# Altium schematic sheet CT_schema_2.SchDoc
size 308 x 312 mm
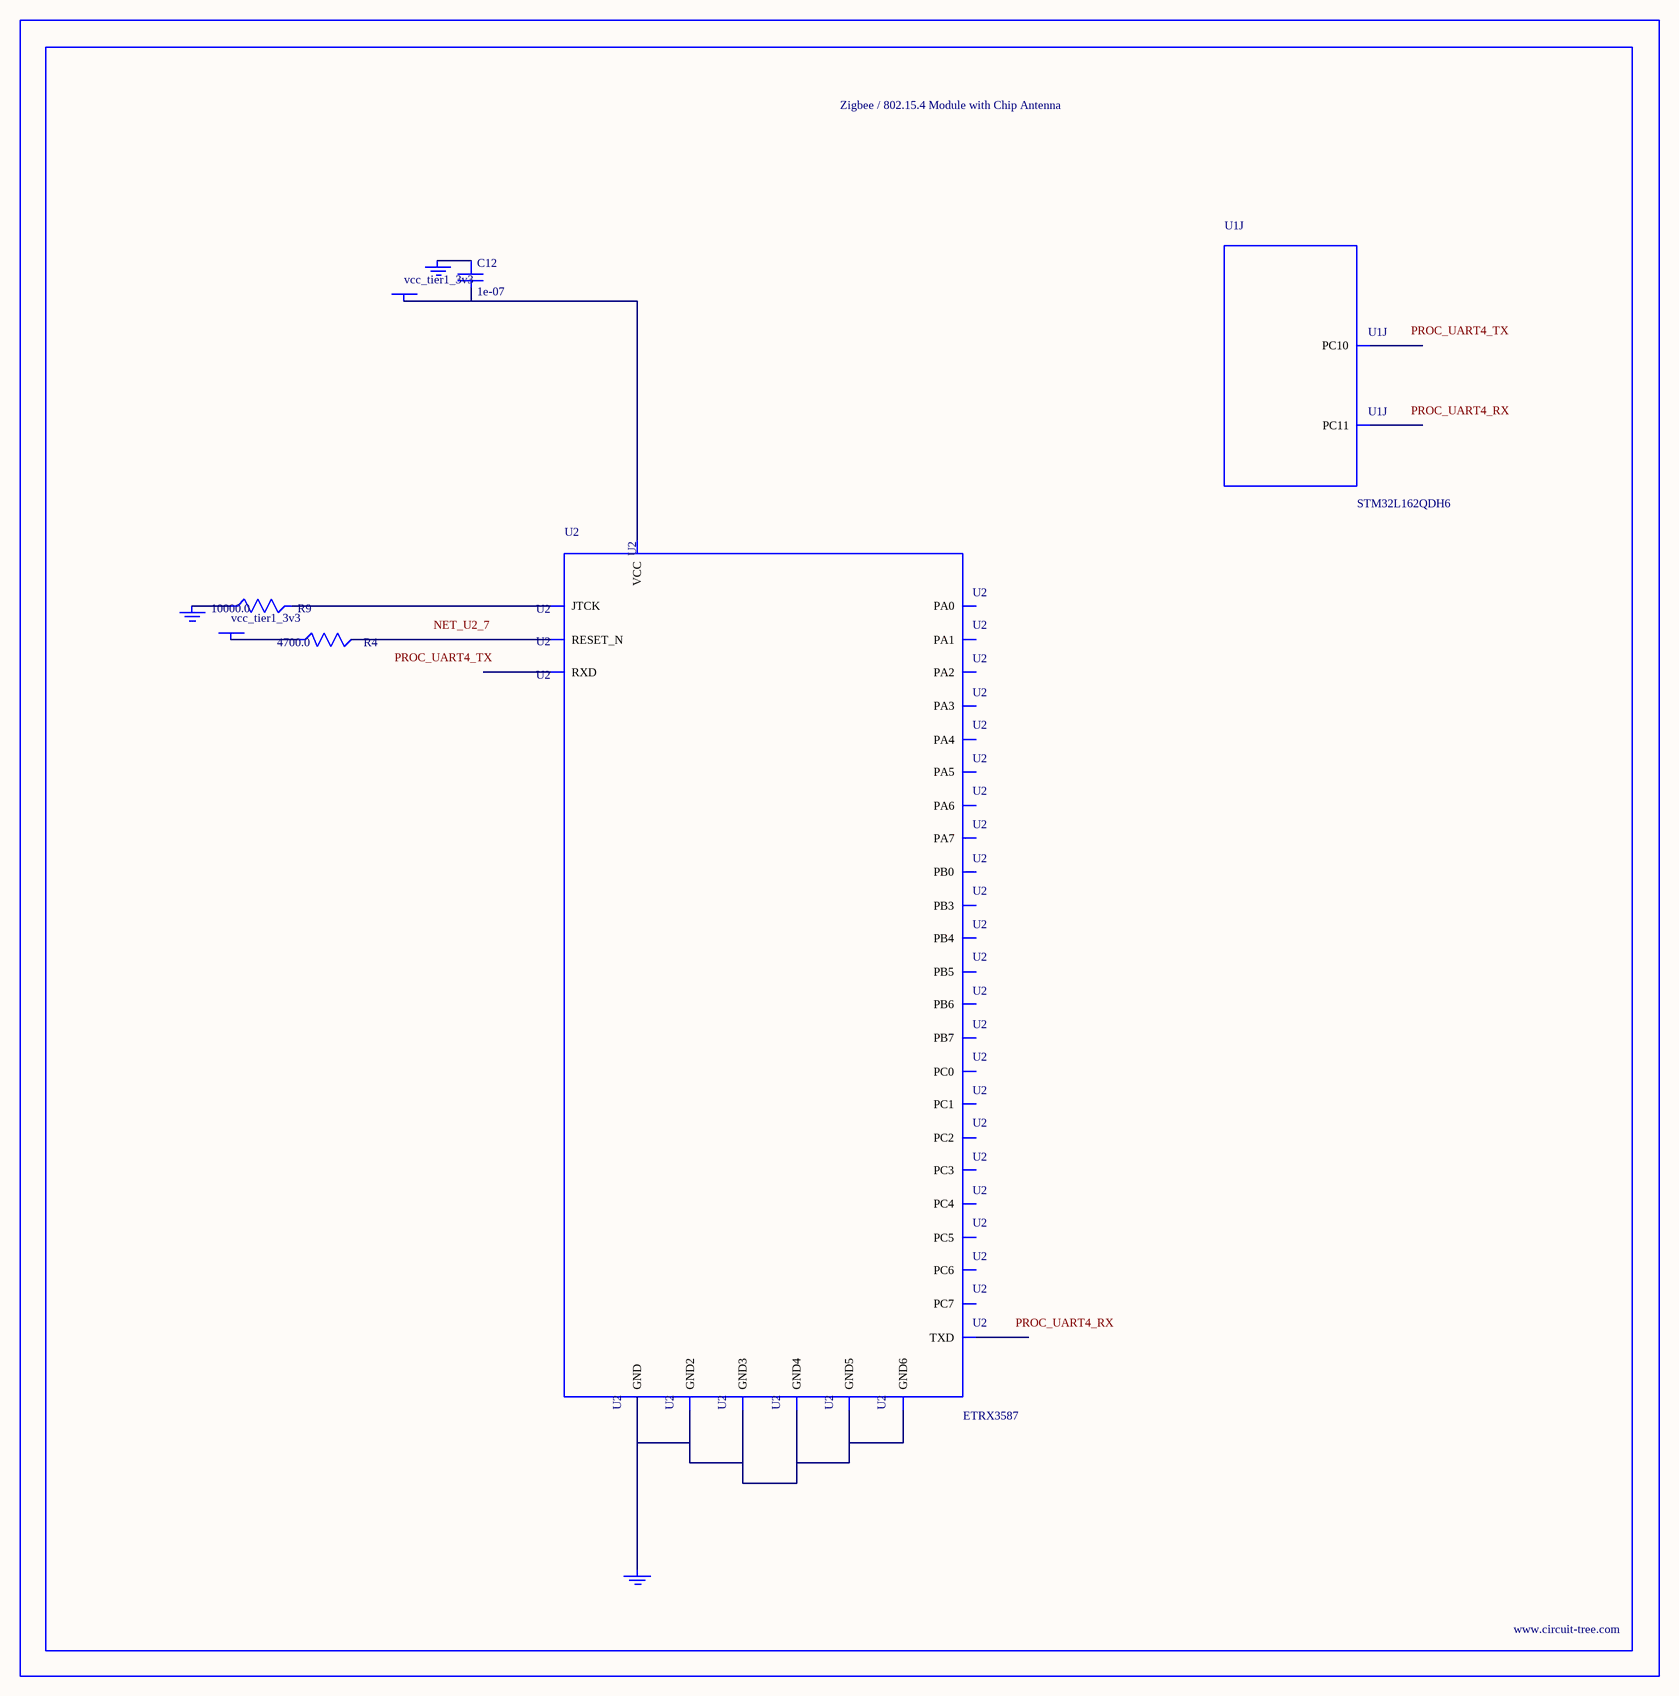
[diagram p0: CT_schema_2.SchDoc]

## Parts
BORDER1  (no value)
C12  1e-07  [C0402]
GND_INSTANCE_1_0  (no value)
GND_INSTANCE_1_1  (no value)
GND_INSTANCE_1_2  (no value)
POWER_INSTANCE_1_0  vcc_tier1_3v3
POWER_INSTANCE_1_1  vcc_tier1_3v3
R4  4700.0  [R0603]
R9  10000.0  [R0603]
U1  STM32L162QDH6  [UFBGA132]  (part J of 12)
U2  ETRX3587  [ETRX3587]

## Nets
NetC12_1: C12.1 GND_INSTANCE_1_1.0(GND)
NetC12_2: C12.2 POWER_INSTANCE_1_0.0(PWR) U2.32(VCC)
NetGND_INSTANCE_1_0_0: GND_INSTANCE_1_0.0(GND) R9.1
NetGND_INSTANCE_1_2_0: GND_INSTANCE_1_2.0(GND) U2.1(GND) U2.13(GND2) U2.19(GND3) U2.20(GND4) U2.31(GND5) U2.33(GND6)
NetPOWER_INSTANCE_1_1_0: POWER_INSTANCE_1_1.0(PWR) R4.1
NetR4_2: R4.2 U2.7(RESET_N)
NetR9_2: R9.2 U2.21(JTCK)

Not connected (* = marked no-connect by the designer): U1 B11(PC10) C10(PC11); U2 2(PC5) 3(PC6) 4(PC7) 5(PA7) 6(PB3) 8(PB4) 9(PA0) 10(PA1) 11(PA2) 12(PA3) 14(PA4) 15(PA5) 16(PA6) 17(TXD) 18(RXD) 22(PC2) 23(PC3) 24(PC4) 25(PB0) 26(PC1) 27(PC0) 28(PB7) 29(PB6) 30(PB5)

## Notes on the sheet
- Labels drawn without touching a wire or pin: NET_U2_7, PROC_UART4_RX, PROC_UART4_TX

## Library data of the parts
BORDER1 = BORDER_PAGE1
C12 = C0402C104K3RACTU
GND_INSTANCE_1_0-GND_INSTANCE_1_2 = GND
POWER_INSTANCE_1_0 POWER_INSTANCE_1_1 = PWR
R4 = RC0603JR-074K7L
R9 = RC0603JR-0710KL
